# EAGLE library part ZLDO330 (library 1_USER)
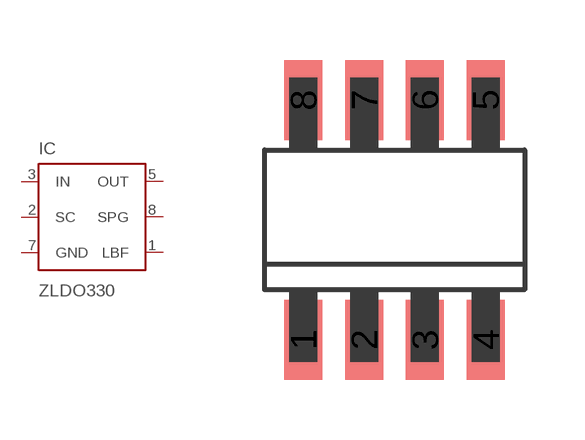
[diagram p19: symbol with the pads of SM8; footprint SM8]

Designator prefix IC

## ZLDO330  [SM8]
1  LBF  out
2  SC  in
3  IN  in
5  OUT  out
7  GND  pwr
8  SPG  in

## Footprint SM8 (pad centres in mm)
smd 0.95 x 2: 1 -2.28,-3; 2 -0.76,-3; 3 0.76,-3; 4 2.28,-3; 5 2.28,3; 6 0.76,3; 7 -0.76,3; 8 -2.28,3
